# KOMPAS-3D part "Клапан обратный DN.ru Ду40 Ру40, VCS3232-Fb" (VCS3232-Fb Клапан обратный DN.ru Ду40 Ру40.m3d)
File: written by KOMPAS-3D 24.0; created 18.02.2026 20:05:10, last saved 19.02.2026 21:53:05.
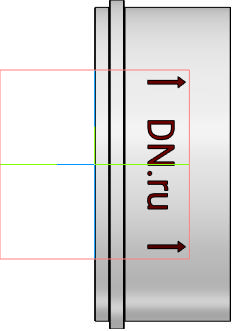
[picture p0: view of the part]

Document properties: Автор: R2D2; Полное имя файла: D:\Работа\Клапаны обратные\VCS3232-Fb Клапан обратный DN.ru Ду15-100\DN40\VCS3232-Fb Клапан обратный DN.ru Ду40 Ру40.m3d

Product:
- Body: Тело 1  | qty 1
    Масса: 0.487013
- Body: Тело 2  | qty 1
    Масса: 0.16409
- Part/product: Клапан обратный DN.ru Ду40 Ру40  | designation VCS3232-Fb
    Масса: 0.64
    Раздел спецификации: Прочие изделия
    Примечание: D100-03709
    additional columns: 1; D100-03709

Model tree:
1. Операция без истории:1
2. Операция без истории:2

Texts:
  Точка начала. Х
  Точка начала. Y
  Точка начала. Z
  VCS3232-Fb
